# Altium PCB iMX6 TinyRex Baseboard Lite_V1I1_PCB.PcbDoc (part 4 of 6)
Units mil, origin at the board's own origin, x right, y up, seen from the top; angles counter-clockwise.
Board outline 3149.61 x 3543.31 mil, 6 copper layers (L1, L2, L3, L4 (PWR), L5, L6), stack 60.634 mil thick; 385 components, 309 nets, 1566 pads, 914 vias.
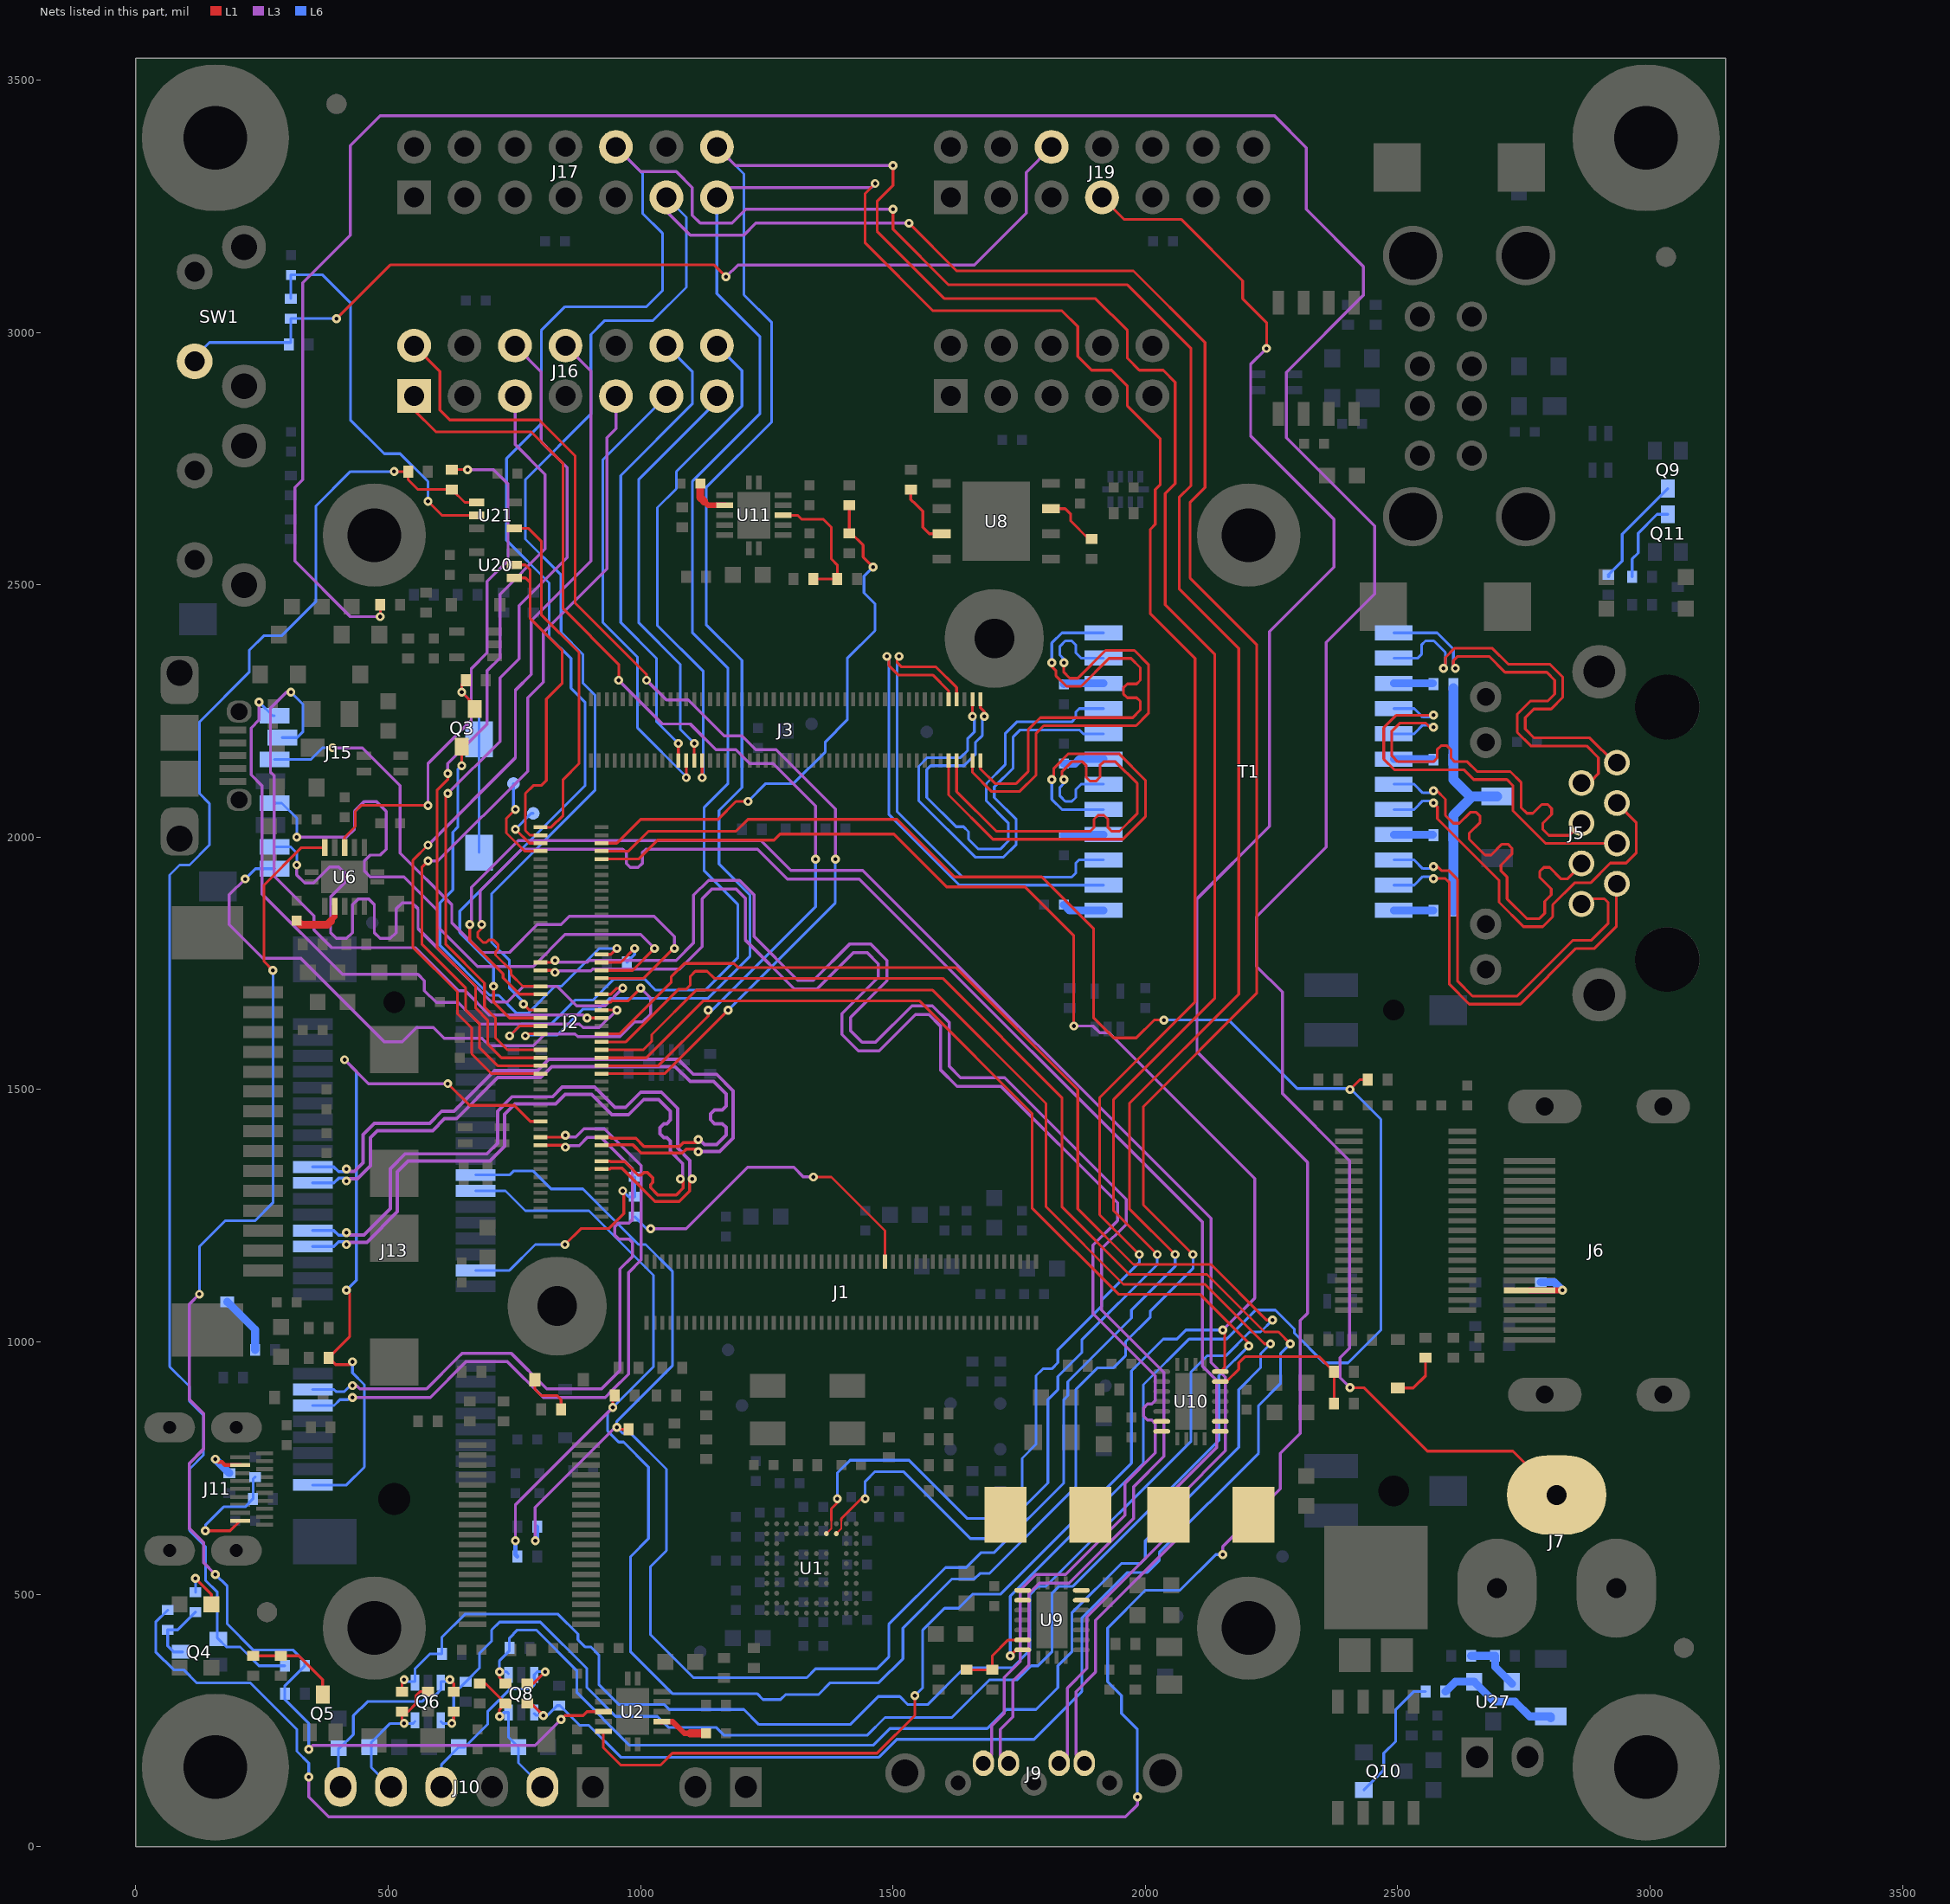
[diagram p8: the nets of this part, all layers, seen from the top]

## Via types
v1: diameter 17.72, hole 7.87, L1 to L6, 471 vias
v2: diameter 17.72, hole 7.87, L1 to L6, tented both sides, 442 vias
v3: diameter 17.72, hole 7.87, L1 to L6, tented top, 1 vias

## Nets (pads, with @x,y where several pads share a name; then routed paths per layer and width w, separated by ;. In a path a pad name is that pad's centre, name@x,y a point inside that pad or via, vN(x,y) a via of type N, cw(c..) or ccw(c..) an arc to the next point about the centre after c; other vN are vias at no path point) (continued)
I2C2_SCL: J2.48 J13.30 J17.11 R9.1 R135.2 | length 8602.5
  L1 w5.4: v2(767.72,1669.29) 779.53,1657.48 J2.48@801.57,1657.48 ; v1(944.88,870.08) 944.88,889.76 R9.1@948.82,893.7 ; v1(1531.5,3216.54) 1625.98,3122.05 1976.38,3122.05 2118.11,2980.31 2118.11,2692.91 2088.39,2663.19 2088.39,2513.98 2220.47,2381.89 2220.47,1690.69 1996.06,1466.28 1996.06,1271.65 v1(2094.49,1173.23)
  L3 w5.9: v1(751.97,606.3) 751.97,677.17 v1(944.88,870.08) ; J17.11@1051.18,3267.72 1051.18,3240.16 1098.43,3192.91 1204.72,3192.91 1228.35,3216.54 v1(1531.5,3216.54)
  L6 w5.4: J13.30@673.23,1299.21 732.28,1299.21 771.65,1259.84 897.64,1259.84 1025.39,1132.09 1025.39,950.59 v1(944.88,870.08) 934.84,860.04 934.84,823.29 956.69,801.44 966.28,801.44 1015.75,751.97 1015.75,610.24 980.32,574.8 980.32,385.83 1062.99,303.15 1230.57,303.15 1242.38,291.34 1277.3,291.34 1286.95,300.98 1352.17,300.98 1375.79,324.61 1472.05,324.61 1519.69,372.24 1519.69,433.07 1617.03,530.41 1661.42,530.41 1672.15,541.14 1690.75,541.14 1862.6,712.99 1862.6,905.91 1905.51,948.82 1937.01,948.82 1960.63,972.44 1960.63,1000 2010.04,1049.41 2010.04,1061.22 2094.49,1145.67 v1(2094.49,1173.23) ; v2@767.72,1673.23 740.16,1700.79 740.16,1755.91 704.72,1791.34 704.72,1887.8 909.45,2092.52 909.45,2281.75 885.83,2305.38 885.83,2362.2 842.52,2405.51 842.52,2519.69 771.65,2590.55 771.65,2708.66 901.57,2838.58 901.57,2996.06 929.13,3023.62 1024.58,3023.62 1090.55,3089.6 1090.55,3228.35 J17.11@1051.18,3267.72
  L6 w8.27: v1(751.97,606.3) 751.97,578.74 R135.2@755.91,574.8
I2C2_SDA: J2.50 J13.32 J17.10 R8.1 R136.2 | length 8871.8
  L1 w5.4: v2(708.66,1704.72) 708.66,1673.23 740.16,1641.73 J2.50@801.57,1641.73 ; v1(952.76,830.71) 956.69,826.77 R8.1@976.38,826.77 R8.1@980.32,826.77 ; v1(1500,3244.09) 1500,3204.72 1610.24,3094.49 1964.57,3094.49 2090.55,2968.5 2090.55,2696.85 2066.93,2673.23 2066.93,2492.13 2185.04,2374.02 2185.04,1688.98 1968.5,1472.44 1968.5,1263.78 v1(2059.06,1173.23)
  L3 w5.9: v1(791.34,606.3) 791.34,672.39 949.65,830.71 v1(952.76,830.71) ; J17.10@951.18,3367.72 1000,3318.9 1070.87,3318.9 1102.36,3287.4 1102.36,3232.28 1118.11,3216.54 1181.1,3216.54 1208.66,3244.09 v1(1500,3244.09)
  L6 w5.4: J13.32@673.23,1330.71 740.16,1330.71 748.03,1338.58 787.4,1338.58 822.83,1303.15 885.83,1303.15 996.06,1192.91 1010.1,1192.91 1062.99,1140.02 1062.99,952.76 952.76,842.52 v1(952.76,830.71) 964.57,818.9 980.32,818.9 1051.18,748.03 1051.18,586.61 1019.69,555.12 1019.69,419.55 1104.59,334.65 1329.16,334.65 1346.68,352.17 1468.05,352.17 1491.61,375.73 1491.61,440.43 1604.13,552.95 1645.22,552.95 1674.94,582.68 1700.79,582.68 1838.58,720.47 1838.58,885.83 1846.46,893.7 1846.46,921.26 1972.44,1047.24 1972.44,1062.99 2059.06,1149.61 v1(2059.06,1173.23) ; v2(708.66,1704.72) 708.66,1744.09 641.73,1811.02 641.73,1853.73 889.76,2101.76 889.76,2267.72 862.2,2295.28 862.2,2354.33 818.9,2397.64 818.9,2503.94 734.45,2588.39 734.45,2750.2 803.15,2818.9 803.15,3003.94 850.39,3051.18 1011.81,3051.18 1043.31,3082.68 1043.31,3196.85 1003.94,3236.22 1003.94,3314.96 J17.10@951.18,3367.72
  L6 w8.27: v1(791.34,606.3) 795.28,610.24 R136.2@795.28,633.86
I2C3_SCL: J2.54 J17.14 U1.B8 | length 6613.3
  L1 w3.94: U1.B8@1387.8,620.08 1397.64,629.92 1397.64,645.67
  L1 w5.4: v2(771.65,1606.3) 775.59,1610.24 J2.54@801.57,1610.24 ; 1397.64,645.67 1397.64,649.61 1437.01,688.98 v1(1444.88,688.98) ; v1(1500,3330.71) 1500,3291.34 1468.5,3259.84 1468.5,3200.79 1602.36,3066.93 1901.57,3066.93 1964.57,3003.94 1964.57,2948.82 1988.19,2925.2 2035.43,2925.2 2059.06,2901.57 2059.06,2700.79 2039.37,2681.1 2039.37,2460.63 2137.8,2362.2 2137.8,1681.1 1937.01,1480.31 1937.01,1259.84 v1(2023.62,1173.23)
  L3 w5.9: J17.14@1151.18,3367.72 1188.19,3330.71 v1(1500,3330.71)
  L6 w5.4: v2(771.65,1606.3) 773.82,1608.46 835.1,1608.46 886.28,1659.65 917.32,1659.65 938.78,1681.1 1133.86,1681.1 1216.54,1763.78 1216.54,1885.83 1155.32,1947.05 1155.32,2052.95 1200.79,2098.43 1200.79,2350.39 1129.92,2421.26 1129.92,2692.91 1259.84,2822.83 1259.84,3019.69 1204.72,3074.8 1204.72,3314.17 J17.14@1151.18,3367.72 ; v1(1444.88,688.98) 1444.88,723.43 1464.57,743.11 1520.67,743.11 1653.54,610.24 1696.85,610.24 1807.09,720.47 1807.09,885.83 1826.77,905.51 1826.77,931.36 1874.02,978.6 1874.02,1003.94 2023.62,1153.54 v1(2023.62,1173.23)
I2C3_SDA: J2.52 J17.13 U1.B7 | length 6460.1
  L1 w3.94: U1.B7@1368.11,620.08 1377.95,629.92 1377.95,645.67
  L1 w5.4: v2(740.16,1606.3) 759.84,1625.98 J2.52@801.57,1625.98 ; 1377.95,645.67 1377.95,669.29 1389.76,681.1 v1(1389.76,688.98) ; v1(1464.57,3295.28) 1444.88,3275.59 1444.88,3177.17 1578.74,3043.31 1834.65,3043.31 1866.14,3011.81 1866.14,2952.76 1893.7,2925.2 1933.07,2925.2 1964.57,2893.7 1964.57,2854.33 2029.72,2789.17 2029.72,2699.02 2019.69,2688.98 2019.69,2619.82 2010.04,2610.18 2010.04,2442.72 2098.43,2354.33 2098.43,1673.23 1909.45,1484.25 1909.45,1251.97 v1(1988.19,1173.23)
  L3 w5.9: J17.13@1151.18,3267.72 1170.87,3287.4 1456.69,3287.4 v1(1464.57,3295.28)
  L6 w5.4: v2@736.22,1606.3 v2@738.19,1608.27 ; v2(740.16,1606.3) 763.78,1629.92 822.83,1629.92 870.08,1677.17 905.51,1677.17 947.05,1718.7 1007.93,1718.7 1029.78,1696.85 1127.7,1696.85 1192.91,1762.07 1192.91,1866.14 1125.98,1933.07 1125.98,2059.06 1173.23,2106.3 1173.23,2334.65 1102.36,2405.51 1102.36,2704.72 1236.22,2838.58 1236.22,2992.13 1151.18,3077.17 J17.13@1151.18,3267.72 ; v1(1389.76,688.98) 1389.76,740.16 1415.16,765.55 1531.69,765.55 1647.24,650 1705.12,650 1755.91,700.79 1755.91,769.43 1783.46,796.99 1783.46,933.07 1797.05,946.65 1814.51,946.65 1826.77,958.92 1826.77,984.25 1913.39,1070.87 1913.39,1082.68 1988.19,1157.48 v1(1988.19,1173.23)
L1_3V3: L2.1 U10.8 U10.9
L1_5V: L1.1 U9.8 U9.9
L2_3V3: L2.2 U10.6 U10.7
L2_5V: L1.2 U9.6 U9.7
MCT0: R87.1 T1.15 | length 76.9
  L6 w15.75: T1.15@2492.22,2304.92 R87.1@2569.09,2304.92
MCT1: R85.1 T1.21 | length 77.7
  L6 w15.75: T1.21@2492.22,2004.92 R85.1@2569.88,2004.92
MCT2: R86.1 T1.18 | length 77.3
  L6 w15.75: T1.18@2492.22,2154.92 R86.1@2569.49,2154.92
MCT3: R84.1 T1.24 | length 78.1
  L6 w15.75: T1.24@2492.22,1854.92 R84.1@2570.28,1854.92
MCT_CHASSIS: C119.1 R84.2 R85.2 R86.2 R87.2 | length 523.4
  L6 w19.68: R84.2@2610.24,1854.33 R85.2@2610.24,2003.94 2610.24,2043.31 2647.64,2080.71 ; R87.2@2610.24,2295.28 R86.2@2610.24,2153.54 2610.24,2114.17 2643.7,2080.71 2647.64,2080.71 ; C119.1@2696.85,2080.71 2647.64,2080.71
MPCIE_WDISN: J1.40 R22.2 | length 669.5
  L1 w5.4: v2(1342.52,1326.77) 1377.95,1326.77 1484.25,1220.47 J1.40@1484.25,1159.06
  L3 w5.9: v2(1019.69,1224.41) 1090.55,1224.41 1212.04,1345.9 1303.71,1345.9 1322.83,1326.77 v2(1342.52,1326.77)
  L6 w5.4: R22.2@988.19,1248.03 1011.81,1224.41 v2(1019.69,1224.41)
MPCIE_WDISN_R: J13.20 R10.1 R22.1 | length 453.9
  L1 w5.4: v2(850.39,1192.91) 881.89,1224.41 937.01,1224.41 966.73,1254.13 966.73,1297.05 v2(964.57,1299.21)
  L6 w5.4: J13.20@673.23,1141.73 740.16,1141.73 791.34,1192.91 v2(850.39,1192.91) ; v2(964.57,1299.21) 976.38,1287.4 R22.1@988.19,1287.4 R10.1@988.19,1326.77
MX0_N: J5.2 T1.13 | length 819.9
  L1 w5.4: v2(2614.17,2334.65) 2610.32,2338.5 2610.32,2349.71 2618.87,2358.27 2681.1,2358.27 2712.6,2326.77 2795.28,2326.77 2811.02,2311.02 2811.02,2283.46 2797.33,2269.77 2763.01,2269.77 2736.82,2243.58 2736.82,2207.9 2763.78,2180.94 2874.18,2180.94 2897.64,2157.48 2897.64,2125.98 2881.89,2110.24 2866.93,2110.24 J5.2@2864.17,2107.48
  L6 w5.4: T1.13@2492.22,2404.92 2578.13,2404.92 2610.32,2372.73 2610.32,2338.5 v2(2614.17,2334.65)
MX0_P: J5.1 T1.14 | length 819.7
  L1 w5.4: v2(2590.55,2334.65) 2594.41,2338.5 2594.41,2356.3 2612.28,2374.18 2687.69,2374.18 2719.19,2342.68 2801.87,2342.68 2826.93,2317.61 2826.93,2276.87 2803.92,2253.86 2769.6,2253.86 2752.73,2236.99 2752.73,2214.49 2770.37,2196.85 2880.77,2196.85 2929.98,2147.64 J5.1@2934.25,2147.64
  L6 w5.4: T1.14@2492.22,2354.92 2539.96,2354.92 2547.24,2362.2 2547.24,2381.14 2555.12,2389.01 2571.54,2389.01 2594.41,2366.14 2594.41,2338.5 v2(2590.55,2334.65)
MX1_N: J5.6 T1.19 | length 818.5
  L1 w5.4: v2(2570.87,2091.73) 2578.09,2091.73 2594.52,2075.31 2594.52,2043.28 2610.24,2027.56 2622.05,2027.56 2643.7,2049.21 2655.51,2049.21 2663.39,2041.34 2663.39,2029.53 2641.73,2007.87 2641.73,1996.06 2673.23,1964.57 2685.04,1964.57 2706.69,1986.22 2718.5,1986.22 2726.38,1978.35 2726.38,1966.54 2704.72,1944.88 2704.72,1933.07 2716.7,1921.1 2716.7,1877.79 2755.74,1838.74 2780.81,1838.74 2791.34,1849.27 2791.34,1872.89 2803.71,1885.27 2804.27,1885.83 2804.27,1897.64 2781.46,1920.45 2781.46,1932.26 2789.33,1940.14 2801.14,1940.14 2823.96,1917.32 2835.77,1917.32 2864.17,1945.73 J5.6@2864.17,1948.03
  L6 w5.4: T1.19@2492.22,2104.92 2532.68,2104.92 2549.72,2087.88 2567.01,2087.88 v2(2570.87,2091.73)
MX1_P: J5.3 T1.20 | length 818.9
  L1 w5.4: v2(2570.87,2068.11) 2578.61,2060.37 2578.61,2036.69 2700.79,1914.51 2700.79,1871.2 2749.15,1822.83 2787.4,1822.83 2807.25,1842.68 2807.25,1866.3 2850.39,1909.45 2881.89,1909.45 2921.26,1948.82 2952.76,1948.82 2972.44,1968.5 2972.44,2029.53 J5.3@2934.25,2067.72
  L6 w5.4: T1.20@2492.22,2054.92 2532.68,2054.92 2549.72,2071.97 2567.01,2071.97 v2(2570.87,2068.11)
MX2_N: J5.5 T1.16 | length 818.5
  L1 w5.4: v2(2570.87,2241.73) 2497.35,2241.73 2472.44,2216.83 2472.44,2154.67 2493.41,2133.7 2631.21,2133.7 2650.73,2114.17 2716.54,2114.17 2728.35,2102.36 2728.35,2052.3 2792.85,1987.79 J5.5@2934.25,1987.79
  L6 w5.4: T1.16@2492.22,2254.92 2532.68,2254.92 2549.72,2237.88 2567.01,2237.88 v2(2570.87,2241.73)
MX2_P: J5.4 T1.17 | length 818.6
  L1 w5.4: v2(2570.87,2218.11) 2563.64,2218.11 2555.93,2225.82 2503.94,2225.82 2488.35,2210.24 2488.35,2161.26 2500,2149.61 2570.87,2149.61 2578.02,2156.76 2578.02,2173.49 2585.89,2181.36 2597.7,2181.36 2605.58,2173.49 2605.58,2156.8 2612.77,2149.61 2637.8,2149.61 2657.32,2130.08 2723.13,2130.08 2744.26,2108.95 2744.26,2058.89 2755.91,2047.24 2767.72,2047.24 2785.43,2064.96 2797.24,2064.96 2805.12,2057.09 2805.12,2045.28 2787.4,2027.56 2787.4,2015.75 2799.45,2003.7 2840.32,2003.7 J5.4@2864.17,2027.56
  L6 w5.4: T1.17@2492.22,2204.92 2532.68,2204.92 2549.72,2221.97 2567.01,2221.97 v2(2570.87,2218.11)
MX3_N: J5.8 T1.22 | length 818.9
  L1 w5.4: v2(2570.87,1941.73) 2578.9,1941.73 2586.61,1934.02 2601,1934.02 2618.27,1916.75 2618.27,1715.25 2648.32,1685.2 2736.38,1685.2 2846.62,1795.44 2883.17,1795.44 2917.16,1829.42 2917.16,1870.24 2909.45,1877.95 2874.41,1877.95 J5.8@2864.17,1867.72
  L6 w5.4: T1.22@2492.22,1954.92 2532.68,1954.92 2549.72,1937.88 2567.01,1937.88 v2(2570.87,1941.73)
MX3_P: J5.7 T1.23 | length 819.7
  L1 w5.4: v2(2570.87,1918.11) 2594.41,1918.11 2602.36,1910.16 2602.36,1708.66 2641.73,1669.29 2742.97,1669.29 2853.21,1779.53 2889.76,1779.53 2933.07,1822.83 2933.07,1906.69 J5.7@2934.25,1907.87
  L6 w5.4: T1.23@2492.22,1904.92 2532.68,1904.92 2549.72,1921.97 2567.01,1921.97 v2(2570.87,1918.11)
NetD3_1: D3.1 R21.1 | length 100.6
  L1 w5.91: D3.1@2500,908.69 2530.74,908.69 2555.12,933.07 R21.1@2555.12,968.5
NetD7_1: D7.1 R50.1 | length 99
  L1 w5.4: D7.1@790.58,925.2 790.58,906.27 803.15,893.7 834.65,893.7 842.52,885.83 R50.1@842.52,866.14
NetD16_1: D16.1 R51.2 | length 118.1
  L6 w15.75: D16.1@181.1,1079.5 236.22,1024.38 R51.2@236.22,984.25
NetJ6_14: J6.14 R14.1 | length 114.4
  L1 w11.81: J6.14@2761.42,1102.36 v2(2826.38,1102.36)
  L6 w15.75: R14.1@2783.46,1118.11 2810.63,1118.11 v2(2826.38,1102.36)
NetJ11_2: J11.2 R39.1 R40.1 | length 249.2
  L1 w5.4: v1(137.8,625.98) 137.99,625.79 186.81,625.79 J11.2@206.69,645.67
  L6 w5.4: v1(137.8,625.98) 137.8,637.07 173.96,673.23 216.54,673.23 R39.1@232.28,688.98 232.28,728.35 R40.1@236.22,732.28
NetJ11_16: J11.16 R162.1 | length 93.1
  L1 w7.87: v1(157.48,767.72) 163.39,761.81 170.59,761.81 176.49,755.91 J11.16@206.69,755.91
  L6 w15.75: v1(157.48,767.72) R162.1@185.04,740.16
NetQ4_3: Q4.3 R144.2 R145.2 | length 135.7
  L6 w5.91: Q4.3@92.52,385.83 74.8,385.83 62.99,397.64 R144.2@62.99,429.13 82.68,429.13 R145.2@118.11,464.57
NetQ5_3: Q5.3 R146.2 R148.2 | length 190.8
  L1 w5.91: R146.2@232.28,377.95 R148.2@287.4,377.95 322.83,377.95 370.08,330.71 Q5.3@370.08,301.18 Q5.3@370.08,297.24
NetQ9_3: Q9.3 R68.2 | length 223
  L6 w5.4: R68.2@2917.32,2515.75 R68.2@2919.29,2517.72 ; R68.2@2917.32,2519.69 2944.88,2547.24 2944.88,2600.39 Q9.3@3035.43,2690.94
NetQ10_1: Q10.1 R293.2 | length 259.3
  L6 w5.4: Q10.1@2433.07,112.2 2472.44,151.57 2472.44,185.04 2496.06,208.66 2496.06,271.65 2531.5,307.09 R293.2@2555.12,307.09
NetQ11_3: Q11.3 R69.2 | length 166.1
  L6 w5.4: R69.2@2964.57,2515.75 2964.57,2551.18 2976.38,2562.99 2976.38,2602.36 3013.78,2639.76 Q11.3@3035.43,2639.76
NetR100_1: R100.1 R293.1 U27.1 | length 250.9
  L6 w15.75: R293.1@2594.49,307.09 2614.17,326.77 U27.1@2651.57,326.77 2690.94,287.4 2732.28,287.4 2761.81,257.87 R100.1@2799.21,257.87 ; R100.1@2803.15,253.94 R100.1@2799.21,257.87 ; R100.1@2803.15,257.87 R100.1@2799.21,257.87
NetR204_2: R204.2 U8.7 | length 113.7
  L1 w5.4: U8.7@1812.99,2650.98 1841.14,2650.98 1852.17,2639.96 1852.17,2626.44 1888.05,2590.55 R204.2@1893.7,2590.55
NetR206_1: R206.1 U8.3 | length 127.5
  L1 w5.91: R206.1@1535.43,2688.98 1535.43,2669.29 1545.27,2659.45 1545.27,2659.39 1559.06,2645.61 1559.06,2614.17 1572.24,2600.98 U8.3@1596.46,2600.98
NetR292_1: R292.1 R296.2 U27.2 | length 116.2
  L6 w15.75: R296.2@2645.67,377.95 R292.1@2692.91,377.95 2692.91,356.3 U27.2@2726.38,322.83
ON_OFF: J2.8 TP11.1 | length 189.4
  L1 w5.4: v1(751.97,2055.12) 734.06,2037.2 734.06,2008.33 769.94,1972.44 J2.8@801.57,1972.44
  L6 w5.4: TP11.1@748.03,2106.3 748.03,2059.06 v1(751.97,2055.12)
PCIE_CLK_N: J2.80 J13.11 | length 1373.8
  L1 w5.4: J2.80@801.57,1405.51 818.31,1405.51 818.39,1405.59 847.33,1405.59 v2(851.18,1409.45)
  L3 w6: v1(429.13,889.76) 583.22,889.76 654.09,960.63 736.22,960.63 807.09,889.76 929.68,889.76 944.09,904.17 976.38,936.46 976.38,1137.25 1001.34,1162.21 1001.34,1349.6 928.34,1422.6 887.96,1422.6 882.68,1417.32 871.54,1406.18 854.45,1406.18 v2(851.18,1409.45)
  L6 w5.4: J13.11@350.39,874.02 392.72,874.02 404.37,885.66 419.89,885.66 423.99,889.76 v1(429.13,889.76)
PCIE_CLK_P: J2.82 J13.13 | length 1373.9
  L1 w5.4: J2.82@801.57,1389.76 818.31,1389.76 818.39,1389.68 847.32,1389.68 v2(851.18,1385.83)
  L3 w6: v1(429.13,913.39) 436.9,913.39 443.44,906.85 576.15,906.85 637.8,968.5 647.01,977.72 743.3,977.72 814.17,906.85 922.6,906.85 959.29,943.54 959.29,1144.33 984.25,1169.29 984.25,1196.85 977.06,1204.04 956.29,1204.04 948.42,1211.91 948.42,1227.66 956.29,1235.54 977.1,1235.54 984.25,1242.69 984.25,1342.52 921.26,1405.51 895.04,1405.51 878.62,1389.09 854.45,1389.09 v2(851.18,1385.83)
  L6 w5.4: J13.13@350.39,905.51 392.72,905.51 396.66,901.57 413.3,901.57 425.12,913.39 v1(429.13,913.39)
PCIE_RX_N: J2.85 J13.23 | length 1367.4
  L1 w6: J2.85@922.83,1358.27 939.61,1358.27 940.99,1356.89 968.5,1356.89 994.94,1330.45 1001.12,1330.45 1006.04,1335.37 1013.64,1335.37 1024.61,1324.41 1024.61,1316.81 1019.69,1311.89 1019.69,1305.71 1034.05,1291.34 1070.87,1291.34 1084.06,1304.53 1084.06,1317.52 v2(1078.74,1322.83)
  L3 w6.7: v1(417.32,1192.91) 421.98,1197.57 457.96,1197.57 518.24,1257.86 518.24,1337.13 539.37,1358.27 701.33,1358.27 730.84,1387.78 730.84,1451.31 751.05,1471.52 831.73,1471.52 850.76,1490.56 903.15,1490.56 943.43,1450.27 976.13,1450.27 1006.17,1480.31 1035.43,1480.31 1059.06,1456.69 1059.06,1439.54 1051.9,1432.39 1046.1,1432.39 1038.23,1424.51 1038.23,1412.7 1046.1,1404.83 1051.87,1404.83 1059.06,1397.64 1059.06,1377.95 1083.4,1353.61 1083.4,1327.5 v2(1078.74,1322.83)
  L6 w6: J13.23@350.39,1188.98 392.32,1188.98 401.57,1198.23 412.01,1198.23 v1(417.32,1192.91)
PCIE_RX_P: J2.87 J13.25 | length 1366.6
  L1 w6: J2.87@922.83,1342.52 939.61,1342.52 940.99,1343.9 963.12,1343.9 1028.67,1278.35 1076.25,1278.35 1097.05,1299.15 1097.05,1317.52 v2(1102.36,1322.83)
  L3 w6.7: v1(417.32,1216.54) 421.98,1211.87 452.03,1211.87 503.94,1263.78 503.94,1343.06 533.45,1372.57 695.4,1372.57 716.54,1393.7 716.54,1457.23 745.13,1485.82 825.81,1485.82 844.84,1504.86 909.07,1504.86 949.36,1464.57 970.2,1464.57 1000.25,1494.61 1041.36,1494.61 1073.36,1462.62 1073.36,1383.88 1097.7,1359.53 1097.7,1327.5 v2(1102.36,1322.83)
  L6 w6: J13.25@350.39,1220.47 392.32,1220.47 401.57,1211.22 412.01,1211.22 v1(417.32,1216.54)
PCIE_TX_N: J2.79 J13.31 | length 1370.7
  L1 w6: J2.79@922.83,1405.51 939.81,1405.51 942.18,1403.15 990.55,1403.15 1006.7,1387.01 1076.9,1387.01 1085.17,1395.27 1108.86,1395.27 v2(1114.17,1400.59)
  L3 w6.7: v1(417.32,1318.9) 421.98,1323.56 438.99,1323.56 464.57,1349.13 464.57,1404.97 478.36,1418.77 588.06,1418.77 611.68,1442.39 635.84,1442.39 717.07,1523.62 802.12,1523.62 824.17,1545.67 1068.5,1545.67 1098.2,1515.97 1144.91,1515.97 1169.29,1491.59 1169.29,1467.1 1162.14,1459.95 1146.5,1459.95 1138.62,1452.07 1138.62,1440.26 1146.5,1432.39 1162.1,1432.39 1169.29,1425.2 1169.29,1409.99 1150.57,1391.27 1126.97,1391.27 1117.65,1400.59 v2(1114.17,1400.59)
  L6 w6: J13.31@350.39,1314.96 392.32,1314.96 401.57,1324.21 412.01,1324.21 v1(417.32,1318.9)
PCIE_TX_P: J2.81 J13.33 | length 1370.4
  L1 w6: J2.81@922.83,1389.76 942.57,1389.76 942.18,1390.16 985.17,1390.16 1001.31,1374.02 1082.28,1374.02 1090.55,1382.28 1108.86,1382.28 v2(1114.17,1376.97)
  L3 w6.7: v1(417.32,1342.52) 421.98,1337.86 433.07,1337.86 450.27,1355.05 450.27,1410.9 472.44,1433.07 582.14,1433.07 605.76,1456.69 629.92,1456.69 711.15,1537.92 796.2,1537.92 818.25,1559.97 1074.42,1559.97 1104.12,1530.27 1150.83,1530.27 1183.59,1497.51 1183.59,1404.06 1156.5,1376.97 v2(1114.17,1376.97)
  L6 w6: J13.33@350.39,1346.46 392.32,1346.46 401.57,1337.2 412.01,1337.2 v1(417.32,1342.52)
PCIE_WAKE: J2.76 J13.1 R37.1 | length 1457.7
  L1 w5.4: v1(417.32,1102.36) 423.43,1096.26 423.43,1010.04 R37.1@381.89,968.5 395.47,954.92 423.43,954.92 v1(429.13,960.63) ; v1(618.11,1511.81) 661.42,1468.5 749.74,1468.5 781.24,1437.01 J2.76@801.57,1437.01
  L3 w5.9: v1(413.39,1559.06) 460.63,1511.81 v1(618.11,1511.81)
  L6 w5.4: J13.1@350.39,716.54 417.32,716.54 452.76,751.97 452.76,915.1 429.13,938.72 v1(429.13,960.63) ; v1(413.39,1559.06) 437.01,1535.43 437.01,1122.05 v1(417.32,1102.36)
PG_+1V5: R153.1 U6.3 | length 1055.2
  L1 w5.4: U6.3@413.39,1979.33 413.39,1999.68 434.84,2021.14 434.84,2051.24 446.59,2062.99 v2(578.74,2062.99) ; R153.1@625.98,2728.35 v1(657.48,2728.35)
  L3 w5.9: v2(578.74,2062.99) 578.74,2145.67 664.57,2231.5 664.57,2333.86 696.06,2365.35 696.06,2507.09 737.4,2548.43 737.4,2699.61 708.66,2728.35 v1(657.48,2728.35)
PMIC_ON_REQ: J2.6 TP14.1 | length 109.5
  L1 w5.4: v1(751.97,2015.75) 779.53,1988.19 J2.6@801.57,1988.19
  L6 w5.4: v1(751.97,2015.75) 783.46,2047.24 TP14.1@787.4,2047.24
POK_1V5_MODULE: J2.5 R31.1 R220.1 | length 1088.4
  L1 w5.4: J2.5@922.83,1988.19 952.76,1988.19 1000,2035.43 1153.54,2035.43 1188.98,2070.87 v1(1212.6,2070.87) ; R31.1@1413.39,2657.48 R220.1@1413.39,2602.36 1417.32,2602.36 1440.94,2578.74 1440.94,2555.12 v2(1460.63,2535.43)
  L6 w5.4: v1(1212.6,2070.87) 1248.03,2106.3 1303.15,2106.3 1366.14,2169.29 1366.14,2188.98 1409.45,2232.28 1409.45,2354.33 1464.57,2409.45 1464.57,2462.4 1442.72,2484.25 1442.72,2517.52 v2(1460.63,2535.43) ; v2@1458.66,2537.4 v2@1460.63,2539.37
POK_1V8: R5.1 R81.1 U2.3 U6.5 | length 2787.8
  L1 w5.4: v1(271.65,1736.22) 253.74,1754.13 253.74,1905.06 328.01,1979.33 U6.5@374.02,1979.33
  L1 w5.91: v1(842.52,251.97) 850.39,259.84 885.83,259.84 893.7,267.72 U2.3@926.18,267.72
  L3 w5.9: v1(125.98,1094.49) 106.3,1074.8 106.3,885.83 133.86,858.27 133.86,787.4 106.3,759.84 106.3,629.92 133.86,602.36 133.86,562.99 v1(157.48,539.37) ; v1(342.52,192.91) 350.39,200.79 791.34,200.79 v1(842.52,251.97)
  L6 w5.4: v1(125.98,1094.49) 125.98,1188.98 177.17,1240.16 236.22,1240.16 271.65,1275.59 v1(271.65,1736.22) ; v1(157.48,539.37) 181.1,515.75 181.1,440.94 232.28,389.76 311.02,389.76 334.65,366.14 R5.1@334.65,358.27 295.28,318.9 R81.1@295.28,303.15 295.28,291.34 342.52,244.09 v1(342.52,192.91)
POK_2V5: R30.1 R224.1 U11.3 | length 259.8
  L1 w5.4: U11.3@1282.48,2637.8 1311.02,2637.8 1318.9,2629.92 1362.2,2629.92 1377.95,2614.17 1377.95,2551.18 1389.76,2539.37 R30.1@1389.76,2511.81 R224.1@1342.52,2511.81
POK_3V3: J2.9 U2.5 U10.14 | length 3944.2
  L1 w5.4: J2.9@922.83,1956.69 996.06,1956.69 1033.66,1994.29 1264.23,1994.29 1276.04,2006.1 1501.77,2006.1 1606.3,1901.57 1761.55,1901.57 1858.27,1804.86 v1(1858.27,1625.98) ; U2.5@926.18,228.35 926.18,195.87 960.63,161.42 1039.37,161.42 1062.99,185.04 1468.5,185.04 1543.31,259.84 v1(1543.31,299.21) ; U10.14@2148.62,940.94 2157.48,949.8 2157.48,1019.68 v1(2153.54,1023.62)
  L3 w5.9: v1(1858.27,1625.98) 1896.48,1625.98 1909.87,1612.6 1927.91,1612.6 2216.54,1323.97 2216.54,1086.61 v1(2153.54,1023.62)
  L6 w5.4: v1(1543.31,299.21) 1559.06,314.96 1559.06,429.13 1602.36,472.44 1629.92,472.44 1657.48,500 1712.6,500 1972.44,759.84 1972.44,942.66 2035.49,1005.71 2062.54,1005.71 2080.45,1023.62 v1(2153.54,1023.62)
POK_5V: J2.7 R26.1 U9.14 | length 3692.7
  L1 w5.4: J2.7@922.83,1972.44 976.38,1972.44 1015.75,2011.81 1188.98,2011.81 1212.6,2035.43 1507.87,2035.43 1622.05,1921.26 1794.69,1921.26 1897.64,1818.31 1897.64,1641.73 1937.01,1602.36 1982.03,1602.36 2017.46,1637.8 v1(2036.55,1637.8) ; v1(1732.28,377.95) 1744.09,389.76 U9.14@1756.89,389.76 ; v2(2405.51,1500) 2425.2,1519.69 R26.1@2440.94,1519.69
  L6 w5.4: v1(1732.28,377.95) 1732.28,496.06 1996.06,759.84 1996.06,915.1 2086.67,1005.71 2160.96,1005.71 2218.25,1062.99 2257.62,1062.99 2295.28,1025.33 2295.28,1017.46 2354.27,958.46 2401.64,958.46 2466.73,1023.56 2466.73,1441.01 2407.74,1500 v2(2405.51,1500) 2403.35,1502.17 2300.98,1502.17 2165.35,1637.8 v1(2036.55,1637.8)
POKN: Q4.1 R5.2 R117.1 R153.2 U21.1 | length 3011.2
  L1 w5.4: v1(511.81,2724.41) R117.1@539.37,2724.41 539.37,2708.66 559.06,2688.98 R153.2@625.98,2688.98 651.57,2663.39 U21.1@675.2,2663.39
  L6 w5.4: R5.2@295.28,358.27 244.09,358.27 206.69,395.67 179.13,395.67 161.42,413.39 161.42,503.94 137.8,527.56 137.8,594.49 106.3,625.98 106.3,748.03 133.86,775.59 133.86,854.33 106.3,881.89 106.3,911.67 66.93,951.04 66.93,1925.2 86.61,1944.88 106.3,1944.88 145.67,1984.25 145.67,2066.93 125.98,2086.61 125.98,2228.35 224.41,2326.77 224.41,2370.08 253.94,2399.61 289.37,2399.61 356.5,2466.73 356.5,2655.71 425.2,2724.41 v1(511.81,2724.41)
PS/SYNC_3V3: R28.1 R29.2 U10.13 | length 328.5
  L1 w5.4: U10.13@2148.62,921.26 2160.43,921.26 2185.04,945.87 2185.04,958.4 2197.3,970.67 2344.29,970.67 R29.2@2374.02,940.94 R28.1@2374.02,877.95
PS/SYNC_5V: R24.1 R25.2 U9.13 | length 151.8
  L1 w5.4: R24.1@1645.67,350.39 R25.2@1696.85,350.39 1696.85,377.95 1728.35,409.45 U9.13@1756.89,409.45
PWR_JACK_INSERTN: J7.3 R63.1 | length 6377.3
  L1 w5.4: v2(484.25,2437.01) R63.1@484.25,2460.63 ; v2(2405.51,909.45) 2433.07,909.45 2559.06,783.46 2728.35,783.46 J7.3@2814.96,696.85
  L3 w5.9: v2(484.25,2437.01) 425.2,2437.01 314.96,2547.24 314.96,2692.91 330.71,2708.66 330.71,3098.43 425.2,3192.91 425.2,3370.08 484.25,3429.13 2255.91,3429.13 2318.9,3366.14 2318.9,3244.09 2432.28,3130.71 2432.28,3074.02 2279.53,2921.26 2279.53,2791.34 2454.33,2616.54 2454.33,2481.89 2358.27,2385.83 2358.27,1980.31 2220.47,1842.52 2220.47,1744.09 2271.65,1692.91 2271.65,1492.13 2404.72,1359.06 2404.72,987.4 2385.83,968.5 2385.83,929.13 v2(2405.51,909.45)
PWR_LED_GRN: D14.1 R145.1 | length 91.8
  L1 w5.4: v1(118.11,531.5) 149.61,500 D14.1@149.61,480.31
  L6 w5.4: R145.1@118.11,503.94 v1(118.11,531.5)
PWR_LED_HDR: J19.7 R144.1 | length 6155.2
  L1 w5.4: J19.7@1914.17,3267.72 1957.48,3224.41 2070.87,3224.41 2192.91,3102.36 2192.91,3066.93 2240.16,3019.69 v1(2240.16,2968.5)
  L3 w5.9: v1(342.52,137.8) 342.52,98.43 381.89,59.06 1960.63,59.06 1984.25,82.68 v1(1984.25,98.43) ; v1(2153.54,578.74) 2153.54,594.49 2267.72,708.66 2267.72,779.53 2307.09,818.9 2307.09,1042.47 2321.26,1056.65 2321.26,1355.91 2102.36,1574.8 2102.36,1877.95 2246.06,2021.65 2246.06,2407.48 2374.02,2535.43 2374.02,2629.92 2208.66,2795.28 2208.66,2937.01 v1(2240.16,2968.5)
  L6 w5.4: R144.1@62.99,468.5 39.37,444.88 39.37,385.83 74.8,350.39 94.55,350.39 120.61,324.33 226.85,324.33 318.9,232.28 318.9,188.98 342.52,165.35 v1(342.52,137.8) ; v1(1984.25,98.43) 1984.25,232.28 1952.76,263.78 1952.76,299.21 1925.2,326.77 1925.2,433.07 2000,507.87 2068.64,507.87 2139.51,578.74 v1(2153.54,578.74)
RST_BTN_HDR: J19.6 R140.1 R141.2 SW1.2 | length 1976.4
  L1 w5.4: v1(397.64,3027.56) 503.94,3133.86 1145.67,3133.86 v1(1169.29,3110.24)
  L3 w5.9: v1(1169.29,3110.24) 1192.91,3133.86 1661.42,3133.86 1763.78,3236.22 1763.78,3317.32 J19.6@1814.17,3367.72
  L6 w5.4: SW1.2@108.46,2942.91 145.87,2980.31 307.09,2980.31 R141.2@307.09,3027.56 v1(397.64,3027.56)
RST_BTNN: C198.1 R141.1 U21.2 | length 771.8
  L1 w5.4: v1(578.74,2665.35) 606.3,2637.8 U21.2@675.2,2637.8
  L6 w5.4: R141.1@307.09,3066.93 C198.1@307.09,3114.17 370.08,3114.17 425.2,3059.06 425.2,2826.77 492.13,2759.84 523.62,2759.84 578.74,2704.72 v1(578.74,2665.35)
SATA_RX_N: J2.36 J9.5 | length 3314.6
  L1 w5.4: J2.36@801.57,1751.97 818.31,1751.97 818.39,1752.05 826.85,1752.05 v2(830.71,1755.91)
  L3 w6: v2(830.71,1755.91) 833.97,1752.64 894.41,1752.64 897.68,1755.91 1070.32,1755.91 1104.96,1790.54 1104.96,1885.03 1134.65,1914.73 1196.06,1914.73 1224.41,1886.37 1224.41,1803.7 1311.57,1716.54 1342.52,1716.54 1414.73,1788.74 1455.47,1788.74 1488.25,1755.96 1488.25,1715.22 1416.04,1643.02 1416.04,1616.43 1438.81,1593.67 1465.39,1593.67 1537.6,1665.87 1578.34,1665.87 1611.12,1633.09 1611.12,1546.36 1633.86,1523.62 1721.02,1523.62 1961.97,1282.67 1961.97,1233.08 1913.39,1184.49 1913.39,1062.99 2036.78,939.6 2036.78,773 1976.38,712.6 1976.38,649.61 1849.05,522.28 1790,522.28 1769.06,501.34 1769.06,359.61 1737.56,328.11 1737.56,257.25 1712.68,232.36 1712.68,181.81 J9.5@1729.13,165.35
SATA_RX_P: J2.38 J9.6 | length 3315.4
  L1 w5.4: J2.38@801.57,1736.22 818.31,1736.22 818.39,1736.14 826.85,1736.14 v2(830.71,1732.28)
  L3 w6: v2(830.71,1732.28) 833.97,1735.55 901.49,1735.55 904.76,1738.82 1077.4,1738.82 1122.05,1783.46 1122.05,1877.95 1141.73,1897.64 1188.98,1897.64 1207.32,1879.29 1207.32,1796.62 1304.49,1699.45 1349.6,1699.45 1421.81,1771.65 1448.39,1771.65 1471.16,1748.88 1471.16,1722.3 1398.95,1650.09 1398.95,1609.35 1431.73,1576.58 1472.47,1576.58 1544.68,1648.78 1571.26,1648.78 1594.03,1626.01 1594.03,1539.28 1626.78,1506.53 1713.94,1506.53 1944.88,1275.59 1944.88,1240.16 1896.3,1191.57 1896.3,1055.91 1905.51,1046.7 2019.69,932.52 2019.69,883.89 2012.53,876.74 2004.18,876.74 1996.3,868.86 1996.3,853.12 2004.18,845.24 2012.5,845.24 2019.69,838.05 2019.69,780.07 1959.29,719.68 1959.29,656.69 1841.97,539.37 1782.92,539.37 1751.97,508.42 1751.97,366.69 1720.47,335.19 1720.47,264.33 1695.59,239.44 1695.59,181.81 J9.6@1679.13,165.35
SATA_TX_N: J2.42 J9.3 | length 3330.3
  L1 w5.4: v2(685.04,1826.77) 685.04,1819.54 677.33,1811.83 677.33,1801.87 687.85,1791.34 694.04,1791.34 698.96,1796.26 708.52,1796.26 717.52,1787.26 717.52,1777.7 712.6,1772.78 712.6,1766.59 743.53,1735.66 743.53,1727.83 766.56,1704.81 785.01,1704.81 785.1,1704.72 J2.42@801.57,1704.72
  L3 w6: v2(685.04,1826.77) 681.77,1826.77 681.77,1893.77 764.38,1976.38 964.57,1976.38 971.72,1969.23 971.72,1948.11 979.59,1940.24 995.3,1940.24 995.34,1940.2 1003.21,1948.07 1003.21,1969.19 1010.4,1976.38 1231.74,1976.38 1290.79,1917.32 1433.07,1917.32 2112.83,1237.56 2112.83,952.13 2141.73,923.23 2141.73,791.34 2051.18,700.79 2051.18,622.05 1884.48,455.35 1884.48,352.99 1845.59,314.09 1845.59,181.81 J9.3@1829.13,165.35
SATA_TX_P: J2.44 J9.2 | length 3330.3
  L1 w5.4: v2(661.42,1826.77) 661.42,1795.28 727.62,1729.07 727.62,1721.24 759.97,1688.9 785.01,1688.9 785.1,1688.98 J2.44@801.57,1688.98
  L3 w6: v2(661.42,1826.77) 664.68,1830.04 664.68,1900.85 757.3,1993.47 1238.82,1993.47 1297.87,1934.41 1440.15,1934.41 2129.92,1244.64 2129.92,959.21 2158.82,930.31 2158.82,784.26 2068.27,693.71 2068.27,614.97 1901.57,448.27 1901.57,345.91 1862.68,307.01 1862.68,181.81 J9.2@1879.13,165.35
SD3_CD: J2.33 Q3.3 | length 905.3
  L1 w5.4: v2(645.67,2141.73) Q3.3@645.67,2179.13 ; J2.33@922.83,1767.72 940.94,1767.72 v2(952.76,1779.53)
  L6 w5.4: v2(645.67,2141.73) 637.8,2133.86 637.8,2019.69 628.15,2010.04 628.15,1895.87 602.36,1870.08 602.36,1785.69 701.24,1686.81 718.7,1686.81 754.13,1651.38 777.36,1651.38 830.71,1704.72 843.44,1704.72 918.25,1779.53 v2(952.76,1779.53)
SD3_CDN: J15.9 J15.10 Q3.1 R201.1 | length 403.1
  L1 w5.4: R201.1@653.54,2311.02 645.67,2303.15 v1(645.67,2287.4) 671.26,2261.81 Q3.1@671.26,2253.94
  L6 w5.4: v1(645.67,2287.4) 680.12,2252.95 J15.9@680.12,2193.9 J15.10@680.12,1969.49
SD3_CLK: J2.37 J15.5 | length 1309
  L1 w5.4: J2.37@922.83,1736.22 984.25,1736.22 v2(1027.56,1779.53)
  L3 w5.9: v1(318.9,2000) 417.32,2000 433.07,2015.75 433.07,2051.18 452.76,2070.87 476.38,2070.87 496.06,2051.18 496.06,1976.38 484.25,1964.57 464.57,1964.57 452.76,1952.76 452.76,1933.07 464.57,1921.26 531.5,1921.26 598.43,1854.33 598.43,1822.83 677.17,1744.09 787.4,1744.09 850.39,1807.09 1000,1807.09 v2(1027.56,1779.53)
  L6 w5.4: J15.5@274.61,2067.52 289.04,2067.52 318.9,2037.66 v1(318.9,2000)
SD3_CMD: J2.39 J15.3 | length 1307.5
  L1 w5.4: J2.39@922.83,1720.47 1006.16,1720.47 1065.22,1779.53 v2(1066.93,1779.53)
  L3 w5.9: v1(389.76,2177.17) 448.82,2177.17 523.62,2102.36 523.62,1968.5 625.98,1866.14 625.98,1830.71 685.04,1771.65 740.16,1771.65 795.28,1826.77 842.52,1826.77 859.05,1843.31 1026.77,1843.31 1066.93,1803.15 v2(1066.93,1779.53)
  L6 w5.4: J15.3@274.61,2154.13 347.05,2154.13 370.08,2177.17 v1(389.76,2177.17)
SD3_DATA0: J2.43 J15.7 | length 1307.1
  L1 w5.4: J2.43@922.83,1688.98 940.94,1688.98 952.76,1700.79 v2(964.57,1700.79)
  L3 w5.9: v1(318.9,1944.88) 318.9,1925.2 334.65,1909.45 352.06,1909.45 383.56,1940.94 401.91,1940.94 414.17,1928.68 414.17,1910.24 385.83,1881.89 385.83,1811.02 397.64,1799.21 417.32,1799.21 429.13,1811.02 429.13,1866.14 440.94,1877.95 460.63,1877.95 472.44,1866.14 472.44,1811.02 484.25,1799.21 503.94,1799.21 515.75,1811.02 515.75,1858.27 527.56,1870.08 547.24,1870.08 559.06,1858.27 559.06,1818.9 704.72,1673.23 736.22,1673.23 767.72,1704.72 834.65,1704.72 873.23,1666.14 929.92,1666.14 v2(964.57,1700.79)
  L6 w5.4: J15.7@274.61,1980.91 306.5,1980.91 318.9,1968.5 v1(318.9,1944.88)
SD3_DATA1: J2.45 J15.8 | length 1306.2
  L1 w5.4: J2.45@922.83,1673.23 940.94,1673.23 943.11,1675.39 974.61,1675.39 v2(1000,1700.79)
  L3 w5.9: v1(216.54,1917.32) 185.04,1885.83 185.04,1826.77 251.97,1759.84 326.77,1759.84 492.13,1594.49 527.56,1594.49 555.91,1622.83 589.76,1622.83 611.02,1601.58 685.83,1601.58 700.79,1586.61 787.4,1586.61 811.02,1610.24 870.08,1610.24 875.59,1604.72 959.06,1604.72 988.19,1633.86 1003.94,1633.86 1019.69,1649.61 1019.69,1681.1 v2(1000,1700.79)
  L6 w5.4: v1(216.54,1917.32) 236.81,1937.6 J15.8@274.61,1937.6
SD3_DATA2: J2.47 J15.1 | length 1305.4
  L1 w5.4: J2.47@922.83,1657.48 v2(952.76,1657.48)
  L3 w5.9: v1(244.09,2267.72) 244.09,2232.28 228.35,2216.54 228.35,2123.62 249.61,2102.36 249.61,1888.19 409.45,1728.35 559.06,1728.35 571.65,1715.75 571.65,1696.06 595.27,1672.44 638.58,1672.44 681.1,1629.92 878.79,1629.92 885.87,1622.83 918.11,1622.83 v2(952.76,1657.48)
  L6 w5.4: v1(244.09,2267.72) 271.06,2240.75 J15.1@274.61,2240.75
SD3_DATA3: J2.49 J15.2 | length 1304.3
  L1 w5.4: v2(893.7,1641.73) J2.49@922.83,1641.73
  L3 w5.9: v1(307.09,2287.4) 298.38,2287.4 266.73,2255.76 266.73,2128.94 273.62,2122.05 273.62,1923.23 353.01,1843.84 353.01,1816.28 388.19,1781.1 553.54,1781.1 638.77,1695.88 652.57,1695.88 700.41,1648.03 886.29,1648.03 892.59,1641.73 v2(893.7,1641.73)
  L6 w5.4: J15.2@290.35,2197.44 319.49,2197.44 330.71,2208.66 330.71,2263.78 v1(307.09,2287.4)
SD3_WP: J2.35 R139.2 | length 110.9
  L1 w5.4: J2.35@922.83,1751.97 960.63,1751.97 v2(988.19,1779.53)
  L6 w5.91: R139.2@972.44,1751.97 988.19,1767.72 v2(988.19,1779.53)
SS_2V5: C92.1 U11.7 | length 82.3
  L1 w11.02: 1125.98,2665.35 1133.86,2657.48 U11.7@1166.34,2657.48
  L1 w15.75: C92.1@1118.11,2700.79 1118.11,2673.23 1125.98,2665.35
SS_+1V5: C21.1 U6.7 | length 105.7
  L1 w11.02: 385.83,1834.65 393.7,1842.52 U6.7@393.7,1863.19
  L1 w15.75: C21.1@318.9,1834.65 326.77,1826.77 379.33,1826.77 386.52,1833.96
SS_+1V8: C59.1 U2.7 | length 97.4
  L1 w11.02: U2.7@1042.32,248.03 1062.99,248.03 1086.61,224.41 1098.43,224.41
  L1 w15.75: 1098.43,224.41 C59.1@1129.92,224.41
SYS_POKN: J2.2 U21.4 | length 705.8
  L1 w5.4: U21.4@750,2612.2 777.56,2612.2 803.15,2586.61 803.15,2440.94 877.95,2366.14 877.95,2145.67 846.46,2114.17 846.46,2043.31 822.83,2019.68 J2.2@801.57,2019.68
SYS_RSTN: J2.4 U20.1 U20.2 | length 686.4
  L1 w5.4: U20.1@750,2513.78 771.91,2513.78 781.3,2504.39 ; U20.2@750,2539.37 771.65,2539.37 781.3,2529.72 781.3,2504.39 ; J2.4@801.57,2003.94 781.04,2003.94 771.65,2013.32 771.65,2086.61 787.4,2102.36 803.15,2102.36 813.39,2112.6 813.39,2274.02 844.69,2305.31 844.69,2369.62 781.3,2433.01 781.3,2504.39
TCT0: C118.2 T1.10 | length 79.4
  L6 w15.75: C118.2@1838.58,2303.15 1840.35,2304.92 T1.10@1917.22,2304.92
TCT1: C116.2 T1.4 | length 79
  L6 w15.75: C116.2@1838.58,2003.94 1839.57,2004.92 T1.4@1917.22,2004.92
TCT2: C117.2 T1.7 | length 82.5
  L6 w15.75: C117.2@1838.58,2145.67 1860.83,2145.67 1870.08,2154.92 T1.7@1917.22,2154.92
TCT3: C114.2 T1.1 | length 83.3
  L6 w15.75: C114.2@1838.58,1866.14 1849.8,1854.92 T1.1@1917.22,1854.92
TRD0_N: J3.1 T1.12 | length 973.4
  L1 w5.4: J3.1@1673.23,2151.97 1673.23,2135.23 1702.16,2106.3 1744.09,2106.3 1767.72,2129.92 1767.72,2212.6 1792.06,2236.94 1975.13,2236.94 1990.16,2251.97 1990.16,2269.12 1983.01,2276.28 1964.32,2276.28 1956.45,2284.15 1956.45,2295.96 1964.32,2303.83 1982.97,2303.83 1990.16,2311.02 1990.16,2335.77 1971.76,2354.17 1927.85,2354.17 1872.73,2299.05 1843.8,2299.05 1822.67,2320.18 1822.67,2330.37 1814.96,2338.08 v2(1814.96,2345.67)
  L6 w5.4: v2(1814.96,2345.67) 1814.8,2345.83 1814.8,2384.88 1834.84,2404.92 T1.12@1917.22,2404.92
TRD0_P: J3.3 T1.11 | length 973.3
  L1 w5.4: J3.3@1657.32,2151.97 1657.32,2128.64 1695.57,2090.39 1750.68,2090.39 1783.63,2123.33 1783.63,2206.01 1798.65,2221.03 1981.72,2221.03 2006.07,2245.38 2006.07,2342.36 1978.35,2370.08 1921.26,2370.08 1866.14,2314.96 1850.39,2314.96 1838.58,2326.77 v2(1838.58,2345.67)
  L6 w5.4: v2(1838.58,2345.67) 1838.58,2352.9 1830.71,2360.77 1830.71,2378.29 1841.43,2389.01 1854.33,2389.01 1862.2,2381.1 1862.2,2365.35 1872.64,2354.92 T1.11@1917.22,2354.92
TRD1_N: J3.7 T1.6 | length 974.7
  L1 w5.4: J3.7@1625.98,2151.97 1625.98,2135.23 1626.06,2135.15 1626.06,2090.47 1704.72,2011.81 1891.17,2011.81 1898.32,2018.96 1898.32,2035.69 1906.2,2043.57 1918.01,2043.57 1925.88,2035.69 1925.88,2019 1933.07,2011.81 1948.82,2011.81 1984.25,2047.24 1984.25,2106.3 1940.94,2149.61 1917.32,2149.61 1910.17,2142.46 1910.17,2118.83 1902.3,2110.96 1890.49,2110.96 1882.61,2118.83 1882.61,2142.42 1875.42,2149.61 1854.41,2149.61 1834.73,2129.92 1834.73,2118.03 v2(1838.58,2114.17)
  L6 w5.4: v2(1838.58,2114.17) 1838.58,2106.95 1830.71,2099.07 1830.71,2081.56 1841.43,2070.83 1854.33,2070.83 ; 1854.33,2070.87 1862.2,2078.74 1862.2,2094.49 1872.64,2104.92 T1.6@1917.22,2104.92
TRD1_P: J3.9 T1.5 | length 974.4
  L1 w5.4: J3.9@1610.24,2151.97 1610.24,2135.23 1610.15,2135.15 1610.15,2083.88 1698.13,1995.9 1955.41,1995.9 2000.16,2040.65 2000.16,2112.89 1947.53,2165.52 1847.82,2165.52 1818.82,2136.51 1818.82,2118.03 v2(1814.96,2114.17)
  L6 w5.4: v2(1814.96,2114.17) 1814.8,2114.01 1814.8,2074.97 1834.84,2054.92 T1.5@1917.22,2054.92
TRD2_N: J3.2 T1.9 | length 971.6
  L1 w5.4: J3.2@1673.23,2273.23 1673.23,2256.5 1681.1,2248.62 v2(1681.1,2239.37)
  L6 w5.4: v2(1681.1,2239.37) 1677.25,2235.51 1677.25,2201.99 1663.59,2188.33 1663.59,2164.71 1640.61,2141.73 1574.8,2141.73 1566.93,2133.86 1566.93,2078.74 1625.02,2020.65 1639.76,2020.65 1649.61,2010.81 1649.61,1996.06 1669.29,1976.38 1712.6,1976.38 1728.35,1992.13 1728.35,2028.68 1684.88,2072.15 1684.88,2106.14 1722.28,2143.54 1722.28,2205.41 1745.38,2228.51 1854.33,2228.51 1862.2,2236.38 1862.2,2248.03 1869.09,2254.92 T1.9@1917.22,2254.92
TRD2_P: J3.4 T1.8 | length 971.7
  L1 w5.4: J3.4@1657.12,2273.23 1657.12,2239.73 v2(1657.48,2239.37)
  L6 w5.4: v2(1657.48,2239.37) 1661.34,2235.51 1661.34,2208.58 1647.68,2194.92 1647.68,2171.3 1634.02,2157.64 1568.21,2157.64 1551.02,2140.45 1551.02,2072.15 1662.7,1960.47 1719.19,1960.47 1744.26,1985.54 1744.26,2035.27 1700.79,2078.74 1700.79,2099.55 1738.19,2136.95 1738.19,2198.82 1751.97,2212.6 1869.09,2212.6 1876.77,2204.92 T1.8@1917.22,2204.92
TRD3_N: J3.8 T1.3 | length 973.2
  L1 w5.4: v2(1511.81,2358.27) 1507.95,2354.41 1507.95,2346.46 1517.04,2337.37 1585.33,2337.37 1626.15,2296.55 J3.8@1626.15,2273.23
  L6 w5.4: v2(1511.81,2358.27) 1507.95,2354.41 1507.95,2051.1 1638.22,1920.83 1853.9,1920.83 1862.2,1929.13 1862.2,1948.82 1868.31,1954.92 T1.3@1917.22,1954.92
TRD3_P: J3.10 T1.2 | length 973.9
  L1 w5.4: v2(1488.19,2358.27) 1492.05,2354.41 1492.05,2339.87 1510.45,2321.46 1578.74,2321.46 1610.24,2289.96 J3.10@1610.24,2273.23
  L6 w5.4: v2(1488.19,2358.27) 1492.05,2354.41 1492.05,2044.51 1631.63,1904.92 T1.2@1917.22,1904.92
UART1_CTS: J2.59 Q6.1 R56.1 R60.1 | length 4074.8
  L1 w5.4: v1(625.98,244.09) 629.92,248.03 R60.1@629.92,267.72 ; J2.59@922.83,1562.99 1011.06,1562.99 1123.46,1675.39 1552.95,1675.39 1775.59,1452.76 1775.59,1265.49 1946.59,1094.49 2108.01,1094.49 2204.72,997.77 v2(2204.72,992.13)
  L6 w5.4: Q6.1@604.33,248.03 608.27,244.09 v1(625.98,244.09) 629.92,248.03 629.92,303.15 R56.1@653.54,326.77 681.1,354.33 681.1,383.6 704.72,407.22 704.72,429.13 720.47,444.88 801.44,444.88 893.7,352.62 893.7,314.96 950.59,258.07 1033.27,258.07 1055.12,236.22 1149.61,236.22 1165.35,220.47 1448.82,220.47 1484.25,255.91 1616.77,255.91 1691.57,330.71 1746.32,330.71 1773.88,358.27 1787.4,358.27 1814.96,385.83 1814.96,501.71 1829,515.75 1856.56,515.75 2145.67,804.86 2145.67,933.07 v2(2204.72,992.13)
UART1_CTS_FTDI: D12.1 J10.6 Q6.6 R60.2 | length 413.2
  L1 w5.4: v1(622.05,330.71) 629.92,322.83 R60.2@629.92,307.09
  L6 w5.4: J10.6@405.51,118.11 401.57,122.05 D12.1@401.57,194.88 403.54,194.88 430.91,222.24 430.91,259.39 458.92,287.4 566.93,287.4 579.53,300 593.56,300 604.33,310.77 Q6.6@604.33,324.8 604.33,326.77 618.11,326.77 v1(622.05,330.71)
UART1_RTS: J2.57 Q8.4 R61.1 R71.1 | length 4053.2
  L1 w5.4: v1(720.47,346.46) 720.47,334.65 R61.1@732.28,322.83 ; J2.57@922.83,1578.74 1005.65,1578.74 1022.13,1595.22 1022.13,1608.75 1110.24,1696.85 1578.74,1696.85 1803.15,1472.44 1803.15,1267.72 1956.69,1114.17 2118.11,1114.17 2236.22,996.06 v2(2248.03,996.06)
  L6 w5.4: Q8.4@738.19,342.52 734.25,346.46 v1(720.47,346.46) 720.47,368.37 740.16,388.05 R71.1@740.16,393.7 740.16,413.39 755.91,429.13 793.05,429.13 874.02,348.17 874.02,304.86 978.09,200.79 1460.63,200.79 1493.9,234.06 1686.81,234.06 1724.41,271.65 1783.46,271.65 1826.77,314.96 1826.77,358.27 1854.33,385.83 1854.33,462.86 1952.3,560.83 1989.96,560.83 2000,570.87 2000,606.3 2185.04,791.34 2185.04,905.51 2228.35,948.82 2228.35,976.38 v2(2248.03,996.06)
UART1_RTS_FTDI: D13.1 J10.2 Q8.3 R57.1 R61.2 | length 294.5
  L1 w5.4: R57.1@681.1,322.83 692.91,322.83 R61.2@732.28,283.46 720.47,271.65 v1(720.47,257.87)
  L6 w5.4: v1(720.47,257.87) 728.35,265.75 Q8.3@738.19,265.75 738.19,216.54 D13.1@757.87,196.85 757.87,165.75 J10.2@805.51,118.11
UART1_RXD: J2.55 Q8.1 R54.1 R58.1 | length 3980.8
  L1 w5.4: R58.1@775.59,283.46 783.46,283.46 v1(807.09,259.84) ; J2.55@922.83,1594.49 970.73,1594.49 1074.86,1698.62 1090.35,1698.62 1098.43,1706.69 1098.43,1724.41 1108.46,1734.45 1131.69,1734.45 1145.67,1720.47 1598.43,1720.47 1834.65,1484.25 1834.65,1267.72 1968.5,1133.86 2122.05,1133.86 2236.22,1019.68 2263.78,1019.68 v2(2287.4,996.06)
  L6 w5.4: Q8.1@789.37,263.78 793.31,259.84 v1(807.09,259.84) 814.96,259.84 834.65,279.53 R54.1@838.58,279.53 840.29,279.53 879.66,240.16 897.64,240.16 960.63,177.17 1472.44,177.17 1507.87,212.6 1779.53,212.6 1874.02,307.09 1874.02,452.76 1964.57,543.31 2003.94,543.31 2027.56,566.93 2027.56,582.68 2224.41,779.53 2224.41,874.02 2267.72,917.32 2267.72,976.38 v2(2287.4,996.06)
UART1_RXD_FTDI: D4.1 J10.4 Q8.6 R58.2 | length 397.9
  L1 w5.4: R58.2@775.59,322.83 787.4,322.83 v1(811.02,346.46)
  L6 w5.4: J10.4@605.51,118.11 605.51,162.6 D4.1@639.76,196.85 651.57,196.85 696.85,242.13 696.85,267.72 741.34,312.2 780.71,312.2 789.37,320.87 Q8.6@789.37,340.55 795.28,346.46 v1(811.02,346.46)
UART1_TXD: J2.53 Q6.4 R59.1 R70.1 | length 4283.9
  L1 w5.4: R59.1@527.56,307.09 527.56,326.77 v1(531.5,330.71) ; J2.53@922.83,1610.24 958.4,1610.24 1060.83,1712.66 1060.83,1723.96 1086.67,1749.8 1185.04,1749.8 1192.91,1741.93 1624.21,1741.93 1866.14,1500 1866.14,1263.78 1976.38,1153.54 2129.92,1153.54 2240.16,1043.31 v2(2251.97,1043.31)
  L6 w5.4: v1(531.5,330.71) 535.43,326.77 553.15,326.77 553.15,352.36 582.68,381.89 R70.1@606.3,381.89 606.3,415.1 651.83,460.63 836.36,460.63 875.79,421.2 875.79,409.9 889.82,395.87 901.12,395.87 917.32,379.66 917.32,321.12 957.15,281.3 1047.18,281.3 1056.83,271.65 1204.72,271.65 1234.45,241.93 1415.16,241.93 1470.67,297.44 1513.58,297.44 1529.72,281.3 1568.7,281.3 1641.73,354.33 1736.22,354.33 1771.65,389.76 1771.65,500 1787.4,515.75 1803.15,515.75 2090.55,803.15 2090.55,940.94 2122.05,972.44 2159.19,972.44 2206.44,1019.68 2228.35,1019.68 v2(2251.97,1043.31)
UART1_TXD_FTDI: D8.1 J10.5 Q6.3 R55.1 R59.2 | length 310.4
  L1 w5.4: v1(531.5,244.09) 527.56,248.03 R59.2@527.56,267.72 539.37,267.72 555.12,283.46 555.12,299.21 562.99,307.09 R55.1@578.74,307.09
  L6 w5.4: J10.5@505.51,118.11 466.54,157.09 466.54,196.85 466.54,206.69 503.94,244.09 v1(531.5,244.09) 549.21,244.09 Q6.3@553.15,248.03
UART2_RXD: J2.63 J16.2 | length 2226.4
  L1 w5.4: J16.2@551.18,2974.02 602.36,2922.83 602.36,2846.46 622.05,2826.77 799.21,2826.77 870.08,2755.91 870.08,2464.57 1011.81,2322.83 v2(1011.81,2311.02) ; J2.63@922.83,1531.5 1047.24,1531.5 v2(1173.23,1657.48)
  L3 w5.9: v2(1011.81,2311.02) 1051.18,2271.65 1094.49,2271.65 1165.35,2200.79 1200.79,2200.79 1228.35,2173.23 1268.55,2173.23 1385.83,2055.95 v2(1385.83,1956.69)
  L6 w5.4: v2(1173.23,1657.48) 1385.83,1870.08 v2(1385.83,1956.69)
UART2_TXD: J2.61 J16.1 | length 2095.3
  L1 w5.4: J16.1@551.18,2874.02 551.18,2846.46 594.49,2803.15 783.46,2803.15 846.46,2740.16 846.46,2452.76 956.69,2342.52 v2(956.69,2311.02) ; J2.61@922.83,1547.24 1035.43,1547.24 1133.86,1645.67 v2(1133.86,1657.48)
  L3 w5.9: v2(956.69,2311.02) 1043.31,2224.41 1098.43,2224.41 1149.61,2173.23 1188.98,2173.23 1216.54,2145.67 1262.62,2145.67 1346.46,2061.84 v2(1346.46,1956.69)
  L6 w5.4: v2(1133.86,1657.48) 1141.73,1657.48 1346.46,1862.2 v2(1346.46,1956.69)
UART3_CTS: J3.77 J16.12 | length 949.2
  L1 w5.4: J3.77@1074.8,2151.97 v2(1074.8,2185.83)
  L6 w5.4: J16.12@1051.18,2974.02 1102.36,2922.83 1102.36,2858.27 960.63,2716.54 960.63,2425.2 1031.5,2354.33 1031.5,2229.13 v2(1074.8,2185.83)
UART3_RTS: J3.75 J16.11 | length 910.4
  L1 w5.4: v2(1090.55,2118.11) J3.75@1090.55,2151.97
  L6 w5.4: J16.11@1051.18,2874.02 925.2,2748.03 925.2,2425.2 993.9,2356.5 993.9,2216.48 1090.55,2119.82 v2(1090.55,2118.11)
UART3_RXD: J3.73 J16.13 | length 832
  L1 w5.4: J3.73@1106.3,2151.97 v2(1106.3,2185.83)
  L6 w5.4: v2(1106.3,2185.83) 1078.74,2213.39 1078.74,2342.52 996.06,2425.2 996.06,2708.66 1151.18,2863.78 J16.13@1151.18,2874.02
UART3_TXD: J3.71 J16.14 | length 1018.3
  L1 w5.4: v2(1122.05,2118.11) J3.71@1122.05,2151.97
  L6 w5.4: v2(1122.05,2118.11) 1124.21,2120.28 1124.21,2328.54 1033.27,2419.49 1033.27,2653.09 1070.87,2690.69 1070.87,2724.41 1200.79,2854.33 1200.79,2924.41 J16.14@1151.18,2974.02
UART4_RXD: J2.60 J16.5 | length 1554.7
  L1 w5.4: v1(618.11,2125.98) 618.11,2114.17 596.65,2092.72 596.65,1781.3 673.23,1704.72 673.23,1661.42 696.85,1637.8 696.85,1590.55 724.41,1562.99 J2.60@801.57,1562.99
  L3 w5.9: v1(618.11,2125.98) 618.11,2145.67 696.06,2223.62 696.06,2329.92 721.26,2355.12 721.26,2481.1 811.02,2570.87 811.02,2718.9 751.18,2778.74 J16.5@751.18,2874.02
UART4_TXD: J2.58 J16.6 | length 1653.4
  L1 w5.4: v1(618.11,2086.61) 614.17,2082.68 614.17,1787.4 690.75,1710.83 690.75,1663.58 712.6,1641.73 712.6,1602.36 736.22,1578.74 J2.58@801.57,1578.74
  L3 w5.9: v1(618.11,2086.61) 721.26,2189.76 721.26,2315.75 759.06,2353.54 759.06,2459.01 854.33,2554.28 854.33,2732.28 803.15,2783.46 803.15,2922.05 J16.6@751.18,2974.02
UART5_RXD: J2.64 J16.8 | length 1770.8
  L1 w5.4: v1(578.74,1984.25) 549.02,1954.53 549.02,1781.69 637.08,1693.63 637.08,1650.32 665.35,1622.05 665.35,1570.87 704.72,1531.5 J2.64@801.57,1531.5
  L3 w5.9: v1(578.74,1984.25) 751.97,2157.48 751.97,2291.34 783.46,2322.83 783.46,2429.13 901.57,2547.24 901.57,2923.62 J16.8@851.18,2974.02
UART5_TXD: J2.62 J16.9 | length 1644.5
  L1 w5.4: v1(578.74,1952.76) 566.93,1940.94 566.93,1787.4 653.54,1700.79 653.54,1657.48 681.1,1629.92 681.1,1582.68 716.54,1547.24 J2.62@801.57,1547.24
  L3 w5.9: v1(578.74,1952.76) 598.43,1952.76 776.38,2130.71 776.38,2276.38 807.09,2307.09 807.09,2405.51 933.07,2531.5 933.07,2791.34 951.18,2809.45 J16.9@951.18,2874.02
